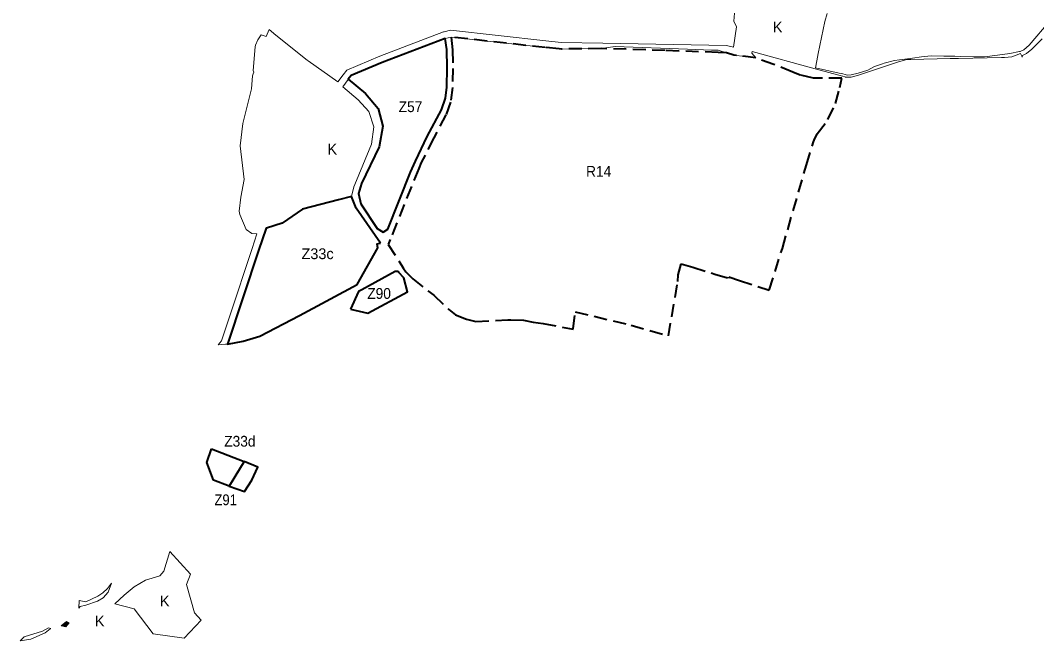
# Model space of a CAD drawing. Extents: x -650276 to -642489, y -1074311 to -1066658.
# Drawn here: x -648979 to -646722, y -1074311 to -1072934 of the extents above; entities that cross this region are included whole.
import ezdxf

# ---------------------------------------------------------------- set-up
doc = ezdxf.new("R2010")
doc.units = 0
doc.header["$LTSCALE"] = 9.6
doc.linetypes.add('MEDIUM_DASHED', pattern=[4.5, 3, -1.5])
for name, color, linetype, lineweight in [('44', 7, 'Continuous', 40), ('45', 7, 'Continuous', 40), ('46', 7, 'Continuous', 13), ('47', 7, 'Continuous', 13), ('48', 7, 'Continuous', 13), ('61', 7, 'MEDIUM_DASHED', 40), ('62', 7, 'Continuous', 35)]:
    doc.layers.add(name, color=color, linetype=linetype, lineweight=lineweight)

msp = doc.modelspace()

# ---------------------------------------------------------------- hatches: boundary and pattern name
at = {"layer": '47'}
msp.add_hatch(color=256, dxfattribs=at).paths.add_polyline_path([(-648876.21, -1074268.73), (-648887.619, -1074278.134), (-648877.799, -1074280.64), (-648870.041, -1074271.932)])

# ---------------------------------------------------------------- linework, layer by layer
at = {"layer": '44'}
msp.add_line((-648245.341, -1073575.152), (-648207, -1073584), dxfattribs=at)
for points in [[(-648139.56, -1073491.4), (-648146.4, -1073491.55), (-648220.42, -1073532.43), (-648227.63, -1073535.89), (-648245.341, -1073575.152)], [(-648207, -1073584), (-648119, -1073537), (-648127.31, -1073505.75), (-648138.41, -1073493.62), (-648139.56, -1073491.4)]]:
    msp.add_lwpolyline(points, dxfattribs=at)
msp.add_lwpolyline([(-648515.333, -1073968.584), (-648480.86, -1073980.25), (-648464.44, -1073954.69), (-648451.05, -1073925.87), (-648481.749, -1073913.76), (-648498, -1073940)], close=True, dxfattribs=at)
at = {"layer": '45'}
for points in [[(-648030.86, -1073039.71), (-648032.09, -1072998.65), (-648035.592, -1072974.222), (-648175.061, -1073027.551), (-648244.214, -1073056.657), (-648250.491, -1073064.698), (-648212.22, -1073096.39), (-648184.37, -1073129.89)], [(-648030.86, -1073039.71), (-648032.09, -1072998.65), (-648035.592, -1072974.222), (-648175.061, -1073027.551), (-648244.214, -1073056.657), (-648250.491, -1073064.698), (-648212.22, -1073096.39), (-648184.37, -1073129.89)], [(-648101.67, -1073246.63), (-648075.34, -1073191.93), (-648043.29, -1073132.97), (-648034.43, -1073107.07), (-648031.8, -1073082.07), (-648030.86, -1073039.71)], [(-648101.67, -1073246.63), (-648075.34, -1073191.93), (-648043.29, -1073132.97), (-648034.43, -1073107.07), (-648031.8, -1073082.07), (-648030.86, -1073039.71)], [(-648184.37, -1073129.89), (-648174.03, -1073168.94), (-648182.12, -1073214.56), (-648221.39, -1073296.24), (-648227.75, -1073318.75), (-648223.03, -1073341.59), (-648186.47, -1073396.47), (-648173.38, -1073404.03)], [(-648184.37, -1073129.89), (-648174.03, -1073168.94), (-648182.12, -1073214.56), (-648221.39, -1073296.24), (-648227.75, -1073318.75), (-648223.03, -1073341.59), (-648186.47, -1073396.47), (-648173.38, -1073404.03)], [(-648173.38, -1073404.03), (-648162.55, -1073397.4), (-648112.36, -1073270.87), (-648101.67, -1073246.63)], [(-648173.38, -1073404.03), (-648162.55, -1073397.4), (-648112.36, -1073270.87), (-648101.67, -1073246.63)], [(-648179.07, -1073428.81), (-648233.36, -1073350.68), (-648243.08, -1073325.04), (-648272.642, -1073332.558)], [(-648179.07, -1073428.81), (-648233.36, -1073350.68), (-648243.08, -1073325.04), (-648272.642, -1073332.558)], [(-648272.642, -1073332.558), (-648352.312, -1073353), (-648397.062, -1073384.375)], [(-648272.642, -1073332.558), (-648352.312, -1073353), (-648397.062, -1073384.375)], [(-648397.062, -1073384.375), (-648432.187, -1073395.625), (-648433.206, -1073395.51), (-648449.599, -1073445.278)], [(-648397.062, -1073384.375), (-648432.187, -1073395.625), (-648433.206, -1073395.51), (-648449.599, -1073445.278)], [(-648447.06, -1073635.39), (-648358.69, -1073589.35), (-648230.81, -1073520.18), (-648185.34, -1073438.91), (-648185.82, -1073435.12), (-648186.46, -1073430.01), (-648183.46, -1073429.52), (-648179.07, -1073428.81)], [(-648447.06, -1073635.39), (-648358.69, -1073589.35), (-648230.81, -1073520.18), (-648185.34, -1073438.91), (-648185.82, -1073435.12), (-648186.46, -1073430.01), (-648183.46, -1073429.52), (-648179.07, -1073428.81)], [(-648449.599, -1073445.278), (-648518.867, -1073652.836), (-648483.58, -1073646.7), (-648447.06, -1073635.39), (-648447.06, -1073635.39)], [(-648449.599, -1073445.278), (-648518.867, -1073652.836), (-648483.58, -1073646.7), (-648447.06, -1073635.39), (-648447.06, -1073635.39)]]:
    msp.add_lwpolyline(points, dxfattribs=at)
msp.add_lwpolyline([(-648554.42, -1073885.092), (-648481.749, -1073913.76), (-648515.333, -1073968.584), (-648549.76, -1073954.86), (-648564.75, -1073915.91)], close=True, dxfattribs=at)
at = {"layer": '47'}
for points in [[(-647392.96, -1072918.277), (-647394.87, -1072936.08), (-647388.62, -1072948.03), (-647395.47, -1072993.25), (-647411.293, -1072989.813), (-647411.294, -1072989.813), (-647411.294, -1072989.813), (-647411.298, -1072989.813), (-647685.748, -1072984.544), (-647778.296, -1072982.767), (-647811.752, -1072979.4), (-648023.495, -1072955.875), (-648023.498, -1072955.876), (-648023.818, -1072955.949), (-648037.595, -1072959.123), (-648038.877, -1072959.418), (-648180.651, -1073013.629), (-648253.635, -1073044.348), (-648261.902, -1073054.939), (-648273.756, -1073070.132), (-648273.756, -1073070.132), (-648339.58, -1073023.82), (-648341.495, -1073022.285), (-648411.09, -1072966.5), (-648426.547, -1072954.108)], [(-646692.432, -1072934.135), (-646739.241, -1072988.798), (-646751.061, -1072999.106), (-646758.883, -1073002.885), (-646760.416, -1073003.25), (-646781.703, -1073007.452), (-646809.778, -1073011.019), (-646838.25, -1073014.938), (-646861.07, -1073014.672), (-646890.523, -1073014.073), (-646904.131, -1073013.793), (-646914.796, -1073013.573), (-646918.156, -1073013.511), (-646928.807, -1073013.313), (-646956.919, -1073012.775), (-646978.077, -1073014.931), (-646997.824, -1073018.092), (-647006.715, -1073019.236), (-647009.402, -1073019.582), (-647026.763, -1073021.811), (-647037.971, -1073023.24), (-647060.677, -1073029.351), (-647064.784, -1073030.747), (-647082.267, -1073036.684), (-647097.466, -1073044.268), (-647118.513, -1073051.327), (-647134.596, -1073054.974), (-647143.312, -1073055.421), (-647147.85, -1073054.204), (-647152.621, -1073052.925), (-647154.999, -1073052.287), (-647161.068, -1073050.946), (-647161.068, -1073050.946), (-647161.068, -1073050.946), (-647213.218, -1073039.42), (-647213.562, -1073039.322), (-647210.396, -1073023.593), (-647207.176, -1073007.598), (-647192.93, -1072936.82), (-647187.445, -1072918.804)], [(-648426.547, -1072954.108), (-648432.527, -1072969.463), (-648443.591, -1072965.983), (-648451.657, -1072977.25), (-648456.2, -1072989.149), (-648457.123, -1072993.118), (-648461.979, -1073045.585), (-648460.355, -1073048.753), (-648461.973, -1073052.688), (-648463.036, -1073057.011), (-648465.708, -1073085.876), (-648484.661, -1073162.812), (-648490.539, -1073212.35), (-648481.853, -1073287.675), (-648489.355, -1073326.567), (-648492.485, -1073357.358), (-648491.34, -1073364.805), (-648477.028, -1073398.055), (-648464.929, -1073407.031), (-648453.228, -1073408.349), (-648463.838, -1073440.559), (-648513.627, -1073589.927), (-648532.252, -1073645.567), (-648539.599, -1073654.802), (-648531.31, -1073654.08), (-648522.79, -1073653.23), (-648518.867, -1073652.836), (-648499.399, -1073594.679), (-648449.599, -1073445.278), (-648433.206, -1073395.51), (-648432.187, -1073395.625), (-648397.062, -1073384.375), (-648378.125, -1073370.875), (-648352.312, -1073353), (-648314.687, -1073343.25), (-648272.642, -1073332.558), (-648243.08, -1073325.04), (-648237.98, -1073303.4), (-648232.64, -1073289.31), (-648198.7, -1073209.08), (-648194.2, -1073170.13), (-648205.04, -1073136.07), (-648228.91, -1073110.54), (-648262.917, -1073081.543), (-648251.027, -1073065.418), (-648250.491, -1073064.698), (-648244.214, -1073056.657), (-648175.061, -1073027.551), (-648035.592, -1072974.222), (-648022.279, -1072971.102), (-647813.331, -1072994.317), (-647782.72, -1072997.397), (-647777.337, -1072997.711), (-647689.11, -1072996.49), (-647658.437, -1072991.865), (-647658.437, -1072991.865), (-647658.437, -1072991.865), (-647658.437, -1072991.865), (-647658.437, -1072991.865), (-647658.437, -1072991.865), (-647497.35, -1072997.93), (-647444.42, -1072999.87), (-647429.276, -1073000.424), (-647411.34, -1073005.89), (-647394.782, -1073011.002), (-647346.22, -1073017.52), (-647354.76, -1073006.65), (-647353.78, -1073003.1), (-647213.99, -1073041.449), (-647153.44, -1073058.06), (-647152.96, -1073058.19), (-647147.91, -1073059.64), (-647147.43, -1073059.78), (-647147.17, -1073059.97), (-647134.03, -1073059.94), (-647118.27, -1073055.88), (-647033.44, -1073027.43), (-647028.91, -1073025.91), (-647026.54, -1073025.11), (-647013.4, -1073021.42), (-647006.15, -1073020.99), (-647001.66, -1073020.72), (-646914.54, -1073019), (-646913.94, -1073018.99), (-646899.22, -1073018.7), (-646895.76, -1073018.63), (-646800.44, -1073016.74), (-646793.8, -1073016.61), (-646777.74, -1073015.29), (-646758.545, -1073007.234), (-646755.58, -1073013.43), (-646754.581, -1073015.554)], [(-646754.581, -1073015.554), (-646753.573, -1073012.306), (-646744.92, -1073007.46), (-646732.95, -1072998.07), (-646710.3, -1072975.31)], [(-648833.449, -1074232.685), (-648807.065, -1074223.704), (-648794.902, -1074216.219), (-648783.863, -1074204.056), (-648775.93, -1074183.91), (-648784.8, -1074195.26), (-648795.65, -1074205.35), (-648806.55, -1074212.62), (-648833.11, -1074225.2), (-648844.05, -1074223.24), (-648848.28, -1074222.49), (-648848.696, -1074238.993)], [(-648848.696, -1074238.993), (-648845.424, -1074235.305), (-648833.449, -1074232.685)]]:
    msp.add_lwpolyline(points, dxfattribs=at)
for points in [[(-648725.93, -1074240.58), (-648683.5, -1074296.12), (-648683.5, -1074296.12), (-648614.6, -1074306.17), (-648577.25, -1074266.06), (-648591.67, -1074249.72), (-648609.49, -1074186.61), (-648600.53, -1074163.47), (-648646.42, -1074113.19), (-648660.16, -1074156.75), (-648669.01, -1074167.27), (-648700.45, -1074176.73), (-648726.23, -1074192.02), (-648747.74, -1074210.12), (-648768.94, -1074229.25)], [(-648876.21, -1074268.73), (-648887.619, -1074278.134), (-648877.799, -1074280.64), (-648870.041, -1074271.932)], [(-648978.575, -1074311.426), (-648955.265, -1074308.325), (-648923.698, -1074294.313), (-648912.63, -1074284.912), (-648910.988, -1074284.211), (-648915.73, -1074283.08), (-648929.03, -1074290.14), (-648970.3, -1074302.9)]]:
    msp.add_lwpolyline(points, close=True, dxfattribs=at)
at = {"layer": '61'}
msp.add_lwpolyline([(-648019.38, -1072999.62), (-648018.59, -1073040.65), (-648019.04, -1073082.7), (-648023.38, -1073115.63), (-648033.71, -1073143.76), (-648060.75, -1073194.72), (-648088.41, -1073249.9), (-648094.092, -1073263.034), (-648157.74, -1073420.89), (-648161.7, -1073431.46), (-648127.64, -1073484.76), (-648122.58, -1073492.69), (-648107.53, -1073507.68), (-648060.92, -1073544.52), (-648027.7, -1073575.75), (-648012.55, -1073588.03), (-647987.9, -1073597.16), (-647967.15, -1073602.95), (-647896.59, -1073598.78), (-647889.64, -1073598.65), (-647861.92, -1073599.87), (-647840.12, -1073604.27), (-647818.3, -1073607.2), (-647751.31, -1073619.66), (-647751.124, -1073618.122), (-647746.63, -1073580.97), (-647622.63, -1073611.03), (-647539.83, -1073634.79), (-647519.11, -1073513.63), (-647518.27, -1073499.08), (-647511.932, -1073474.5), (-647486.04, -1073482.326), (-647436.7, -1073497.24), (-647406.33, -1073506.42), (-647405.5, -1073503.75), (-647382.45, -1073511.28), (-647316.269, -1073532.9), (-647287.03, -1073440.3), (-647233.5, -1073254.63), (-647218, -1073203.36), (-647216.34, -1073199.89), (-647209.63, -1073185.84), (-647185.73, -1073154.33), (-647168.83, -1073118.8), (-647159.72, -1073083.31), (-647154.77, -1073062.68), (-647218.06, -1073062.37), (-647247.46, -1073055.63), (-647263.8, -1073049), (-647305.94, -1073031.89), (-647346.22, -1073017.52), (-647394.782, -1073011.002), (-647411.34, -1073005.89), (-647429.65, -1073005.19), (-647547.02, -1073001.04), (-647689.11, -1072996.49), (-647777.336, -1072997.711), (-647782.72, -1072997.397), (-647813.331, -1072994.317), (-648022.279, -1072971.102)], close=True, dxfattribs=at)

# ---------------------------------------------------------------- texts
at = {"layer": '44'}
for s, width, p in [('Z90', 0.95, (-648208.451, -1073552.422)), ('Z90', 0.95, (-648208.451, -1073552.422)), ('Z91', 0.9, (-648547.629, -1074010.653))]:
    msp.add_text(s, height=24, dxfattribs=dict(at, width=width)).set_placement(p)
at = {"layer": '46', "width": 0.95}
for s, p in [('Z57', (-648138.747, -1073137.744)), ('Z57', (-648138.747, -1073137.744)), ('Z33d', (-648525.981, -1073880.565))]:
    msp.add_text(s, height=24, dxfattribs=at).set_placement(p)
at = {"layer": '46'}
msp.add_text('Z33c', height=24, dxfattribs=at).set_placement((-648354.418, -1073464.218))
msp.add_text('Z33c', height=24, dxfattribs=at).set_placement((-648354.418, -1073464.218))
at = {"layer": '48'}
for p in [(-647307.985, -1072960.845), (-647307.985, -1072960.845), (-648296.955, -1073231.892), (-648668.641, -1074235.329), (-648812.985, -1074279.86)]:
    msp.add_text('K', height=24, dxfattribs=at).set_placement(p)
at = {"layer": '62', "width": 0.95}
msp.add_text('R14', height=24, dxfattribs=at).set_placement((-647722.71, -1073281.294))

doc.saveas('drawing.dxf')
